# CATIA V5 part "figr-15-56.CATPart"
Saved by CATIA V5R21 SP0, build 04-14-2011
Part number: Part1
Bounding box of the stored display mesh (mm): x -75 to -29.087, y -20 to 20, z 0 to 62.461
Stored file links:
  D:\CATIA V5R21 E-RESOURCES\CATIA-V5R21\catia-v5r21-prt\c15-catia-v5r20-prt\c15-catia-v5r21-figr-15-56.CATPart
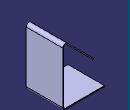
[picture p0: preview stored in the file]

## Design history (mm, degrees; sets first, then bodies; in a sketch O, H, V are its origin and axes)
SheetMetalParameters1: Thickness 1, BendRadius 2, KFactor 0.400515 {= log(min(100,max(20*SheetMetalParameters1.BendRadius,SheetMetalParameters1.Thickness)/SheetMetalParameters1.Thickness))/log(100)/2}, ReliefRadialLength 1, ReliefAxialLength 2, MinimumBendRadius 0
Body1 (main body)
  Sketch1 on xy-plane, origin (0, 0, 0), H (1, 0, 0), V (0, 1, 0)
    line L1 (-75, 20) -> (75, 20)
    line L2 (75, 20) -> (75, -20)
    line L3 (75, -20) -> (-75, -20)
    line L4 (-75, -20) -> (-75, 20)
    distance L1 L3 = 40
    distance L2 L4 = 150
    distance V L2 = 75
    distance H L3 = 20
    horizontal: L1 H, L3 H
    vertical: L2 V, L4 V
  Wall1: Thickness 1, Profile Sketch1
  Sketch2 on face of Wall1, origin (0, 0, 1), H (1, 0, 0), V (0, 1, 0)
    line L1 (-30.2021, 19.5432) -> (-30.2021, -20.6466)
    line L2 (31.0296, 19.5432) -> (31.0296, -20.6466)
    vertical: L1 V, L2 V
  FlatBend1: FlatBendAngle 90, FlatBendAngle 45, Axis Sketch2, FixedPoint vertex [face of Wall1 | face of Wall1 | face of Wall1], FlatBendKFactor 0.400515 {= log(min(100,max(20*FlatBend1.FlatBendRadius,SheetMetalParameters1.Thickness)/SheetMetalParameters1.Thickness))/log(100)/2}, FlatBendKFactor 0.400515 {= log(min(100,max(20*FlatBend1.FlatBendRadius,SheetMetalParameters1.Thickness)/SheetMetalParameters1.Thickness))/log(100)/2}, FlatBendRadius 2 {= SheetMetalParameters1.BendRadius}, FlatBendRadius 2 {= SheetMetalParameters1.BendRadius}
